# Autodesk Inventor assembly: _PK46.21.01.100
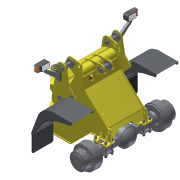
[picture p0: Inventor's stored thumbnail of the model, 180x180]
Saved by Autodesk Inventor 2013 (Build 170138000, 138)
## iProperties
Created: 2005-04
Part Number: _PK46.21.01.100
Document SubType Name: Assembly
Designer: salex
Manufacturer: Standard
Standards Organization: Custom
Author: salex
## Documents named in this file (46)
- C:\Product Design Suite 2013 Test Drive\Inventor to Showcase\Workspace\Assy, Chassis, Front\_PK46.21.01.100.iam
- C:\Product Design Suite 2013 Test Drive\Inventor to Showcase\Workspace\Assy, Chassis, Front\PK46.21.01.010.iam
- C:\Product Design Suite 2013 Test Drive\Inventor to Showcase\Workspace\Assy, Chassis, Front\PK46.21.01.020.iam
- C:\Product Design Suite 2013 Test Drive\Inventor to Showcase\Workspace\Assy, Chassis, Front\PK46.21.01.030.iam
- C:\Product Design Suite 2013 Test Drive\Inventor to Showcase\Workspace\Assy, Chassis, Front\PK46.21.01.040.iam
- C:\Product Design Suite 2013 Test Drive\Inventor to Showcase\Workspace\Assy, Chassis, Front\PK46.21.01.050.iam
- C:\Product Design Suite 2013 Test Drive\Inventor to Showcase\Workspace\Assy, Chassis, Front\PK46.21.01.060.iam
- C:\Product Design Suite 2013 Test Drive\Inventor to Showcase\Workspace\Assy, Chassis, Front\PK46.21.01.070.iam
- C:\Product Design Suite 2013 Test Drive\Inventor to Showcase\Workspace\Assy, Chassis, Front\PK46.21.01.025.ipt
- C:\Product Design Suite 2013 Test Drive\Inventor to Showcase\Workspace\Assy, Chassis, Front\PK46.21.01.026.ipt
- C:\Product Design Suite 2013 Test Drive\Inventor to Showcase\Workspace\Assy, Chassis, Front\PK46.21.01.027.ipt
- C:\Product Design Suite 2013 Test Drive\Inventor to Showcase\Workspace\Assy, Chassis, Front\PK46.21.01.028.ipt
- C:\Product Design Suite 2013 Test Drive\Inventor to Showcase\Workspace\Assy, Chassis, Front\PK46.21.01.029.ipt
- C:\Product Design Suite 2013 Test Drive\Inventor to Showcase\Workspace\Assy, Chassis, Front\PK46.21.01.031.ipt
- C:\Product Design Suite 2013 Test Drive\Inventor to Showcase\Workspace\Assy, Chassis, Front\027.32.02.621.ipt
- C:\Product Design Suite 2013 Test Drive\Inventor to Showcase\Workspace\Assy, Chassis, Front\Bar.ipt
- C:\Product Design Suite 2013 Test Drive\Inventor to Showcase\Workspace\Assy, Chassis, Front\PK46.21.01.035.ipt
- C:\Product Design Suite 2013 Test Drive\Inventor to Showcase\Workspace\Assy, Chassis, Front\PK46.21.01.036.ipt
- C:\Product Design Suite 2013 Test Drive\Inventor to Showcase\Workspace\Assy, Chassis, Front\PK46.21.01.032_1.ipt
- C:\Product Design Suite 2013 Test Drive\Inventor to Showcase\Workspace\Assy, Chassis, Front\_PK46.21.01.080.iam
- C:\Product Design Suite 2013 Test Drive\Inventor to Showcase\Workspace\Assy, Chassis, Front\ODM.73.001-6.iam
- C:\Product Design Suite 2013 Test Drive\Inventor to Showcase\Workspace\Assy, Chassis, Front\PK46.16.10.000.iam
- C:\Product Design Suite 2013 Test Drive\Inventor to Showcase\Workspace\Assy, Chassis, Front\PK46.04.00.002.ipt
- C:\Product Design Suite 2013 Test Drive\Inventor to Showcase\Workspace\Assy, Chassis, Front\PK46.04.00.030.iam
- C:\Product Design Suite 2013 Test Drive\Inventor to Showcase\Workspace\Assy, Chassis, Front\027.13.14.227.ipt
- C:\Product Design Suite 2013 Test Drive\Inventor to Showcase\Workspace\Assy, Chassis, Front\027.13.12.227.ipt
- C:\Product Design Suite 2013 Test Drive\Inventor to Showcase\Workspace\Assy, Chassis, Front\PK46.53.20.000.iam
- C:\Product Design Suite 2013 Test Drive\Inventor to Showcase\Workspace\Assy, Chassis, Front\Part 3.ipt
- C:\Product Design Suite 2013 Test Drive\Inventor to Showcase\Workspace\Assy, Chassis, Front\PK46.43.00.005.ipt
- C:\Product Design Suite 2013 Test Drive\Inventor to Showcase\Workspace\Assy, Chassis, Front\Flap.ipt
- C:\Product Design Suite 2013 Test Drive\Inventor to Showcase\Workspace\Assy, Chassis, Front\PK46.25.00.020.iam
- C:\Product Design Suite 2013 Test Drive\Inventor to Showcase\Workspace\Assy, Chassis, Front\PK46.25.00.006.ipt
- C:\Product Design Suite 2013 Test Drive\Inventor to Showcase\Workspace\Assy, Chassis, Front\PK46.25.00.008.ipt
- C:\Product Design Suite 2013 Test Drive\Inventor to Showcase\Workspace\Assy, Chassis, Front\PK46.25.00.007.ipt
- C:\Product Design Suite 2013 Test Drive\Inventor to Showcase\Workspace\Assy, Chassis, Front\PK46.25.00.010.iam
- C:\Product Design Suite 2013 Test Drive\Inventor to Showcase\Workspace\Assy, Chassis, Front\PK46.25.00.005.ipt
- C:\Product Design Suite 2013 Test Drive\Inventor to Showcase\Workspace\Assy, Chassis, Front\PK46.41.00.200-01.iam
- C:\Product Design Suite 2013 Test Drive\Inventor to Showcase\Workspace\Assy, Chassis, Front\PK46.20.10.000.iam
- C:\Product Design Suite 2013 Test Drive\Inventor to Showcase\Workspace\Assy, Chassis, Front\PK46.04.00.031.iam
- C:\Product Design Suite 2013 Test Drive\Inventor to Showcase\Workspace\Assy, Chassis, Front\027.13.15.227.ipt
- C:\Product Design Suite 2013 Test Drive\Inventor to Showcase\Workspace\Assy, Chassis, Front\027.13.16.227.ipt
- C:\Product Design Suite 2013 Test Drive\Inventor to Showcase\Workspace\Assy, Chassis, Front\PK46.41.00.200-02.iam
- C:\Product Design Suite 2013 Test Drive\Inventor to Showcase\Workspace\Assy, Chassis, Front\PK46.53.20.001.iam
- Bar.ipt
- Part 3.ipt
- Flap.ipt
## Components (106 placed, 42 different names)
1. PK46.21.01.010:1 [sub-assembly] — Mate:1, Mate:3, Mate:6, Mate:9, Angle:1, Mate:10, Flush:3, Angle:4, Mate:17, Mate:18, Mate:19, Mate:33, Mate:34, Mate:45, Mate:54, Mate:61, Mate:67, Mate:68, Mate:73, Angle:8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
2. PK46.21.01.020:1 [sub-assembly] — Mate:2, Mate:4, Mate:6, Mate:8, Mate:39, Mate:40, Mate:59, Mate:66, Mate:69, Mate:72, Angle:7, Flush:16, Mate:100
3. PK46.21.01.030:1 [sub-assembly] — Mate:17, Mate:23, Mate:24, Mate:25, Tangent:1, Tangent:2, Tangent:3, Mate:79, Mate:80
4. PK46.21.01.040:1 [sub-assembly] — Mate:3, Mate:4, Mate:7, Flush:2, Mate:13, Angle:2, Angle:5
5. PK46.21.01.050:1 [sub-assembly] — Mate:1, Mate:2, Mate:7, Flush:2, Angle:4, Angle:6, Mate:55, Mate:64, Mate:65, Mate:70, Mate:71
6. PK46.21.01.060:1 [sub-assembly] — Mate:9, Flush:1, Angle:1, Mate:10, Mate:11, Flush:3, Mate:16, Mate:35, Mate:36, Mate:37, Mate:38, Mate:46, Mate:50, Mate:56, Flush:5, Mate:47, Mate:75
7. PK46.21.01.070:1 [sub-assembly] — Mate:8, Flush:1, Mate:11, Mate:41, Mate:42, Mate:43, Mate:44, Mate:49, Mate:53, Mate:57, Flush:6
8. _PK46.21.01.080:1 [sub-assembly] — Mate:32, Mate:54, Mate:55, Angle:9
9. ODM.73.001-6:1 [sub-assembly]
10. Flap:1
11. PK46.53.20.000:1 [sub-assembly]
12. PK46.25.00.020:4 [sub-assembly]
13. PK46.25.00.006:5
14. PK46.41.00.200-01:1 [sub-assembly]
15. PK46.43.00.005:1
16. PK46.43.00.005:2
17. PK46.25.00.006:8
18. PK46.25.00.008:4
19. PK46.25.00.007:4
20. PK46.25.00.010:1 [sub-assembly]
21. PK46.25.00.005:1
22. PK46.25.00.007:2
23. PK46.25.00.008:2
24. PK46.25.00.006:4
25. PK46.25.00.006:3
26. PK46.25.00.020:1 [sub-assembly]
27. PK46.04.00.002:1
28. PK46.04.00.030:1 [sub-assembly]
29. PK46.04.00.030:2 [sub-assembly]
30. PK46.04.00.030:3 [sub-assembly]
31. PK46.04.00.030:4 [sub-assembly]
32. 027.13.14.227:1
33. 027.13.14.227:2
34. 027.13.14.227:3
35. 027.13.14.227:4
36. 027.13.12.227:1
37. 027.13.12.227:2
38. 027.13.12.227:3
39. 027.13.12.227:4
40. PK46.16.10.000:1 [sub-assembly]
41. Part 3:1
42. Part 3:2
43. PK46.20.10.000:3 [sub-assembly]
44. PK46.20.10.000:4 [sub-assembly]
45. PK46.04.00.031:3 [sub-assembly]
46. PK46.04.00.031:4 [sub-assembly]
47. 027.13.15.227:3
48. 027.13.15.227:4
49. 027.13.16.227:3
50. 027.13.16.227:4
51. PK46.53.20.001:1 [sub-assembly]
52. PK46.25.00.020:3 [sub-assembly]
53. PK46.25.00.020:2 [sub-assembly]
54. PK46.25.00.006:2
55. PK46.25.00.008:1
56. PK46.25.00.007:1
57. PK46.25.00.008:3
58. PK46.25.00.007:3
59. PK46.25.00.006:7
60. PK46.25.00.005:2
61. PK46.25.00.008:5
62. PK46.25.00.007:5
63. PK46.43.00.005:3
64. PK46.43.00.005:4
65. PK46.25.00.006:1
66. PK46.25.00.006:6
67. PK46.41.00.200-02:1 [sub-assembly]
68. PK46.04.00.030:5 [sub-assembly]
69. PK46.04.00.030:7 [sub-assembly]
70. 027.13.14.227:5
71. 027.13.14.227:8
72. 027.13.12.227:5
73. 027.13.12.227:8
74. PK46.04.00.030:6 [sub-assembly]
75. PK46.04.00.030:8 [sub-assembly]
76. 027.13.14.227:6
77. 027.13.14.227:7
78. 027.13.12.227:6
79. 027.13.12.227:7
80. 027.13.16.227:1
81. 027.13.15.227:1
82. PK46.04.00.031:1 [sub-assembly]
83. PK46.20.10.000:1 [sub-assembly]
84. 027.13.16.227:2
85. 027.13.15.227:2
86. PK46.04.00.031:2 [sub-assembly]
87. PK46.20.10.000:2 [sub-assembly]
88. PK46.21.01.032_1:1
89. PK46.21.01.032_1:2
90. PK46.21.01.025:1 — Mate:45, Mate:46, Flush:4, Mate:47, Mate:48, Mate:74
91. PK46.21.01.026:1 — Mate:52, Mate:53, Mate:58, Mate:60, Flush:4
92. PK46.21.01.027:1 — Mate:49, Mate:50, Mate:51, Mate:52, Mate:48
93. PK46.21.01.028:1 — Mate:56, Mate:58, Mate:61
94. PK46.21.01.028:2 — Mate:57, Mate:59, Mate:60
95. PK46.21.01.029:1 — Mate:64, Mate:67
96. PK46.21.01.029:2 — Mate:65, Mate:66
97. PK46.21.01.031:1 — Mate:68, Flush:5, Mate:70
98. PK46.21.01.031:2 — Mate:69, Flush:6, Mate:71
99. 027.32.02.621:1 — Mate:33, Mate:36, Mate:37
100. 027.32.02.621:2 — Mate:34, Mate:35, Mate:38
101. 027.32.02.621:3 — Mate:40, Mate:41, Mate:44
102. 027.32.02.621:4 — Mate:39, Mate:42, Mate:43
103. PK46.21.01.036:1 — Mate:72, Tangent:1, Tangent:2, Angle:7
104. PK46.21.01.035:1 — Mate:73, Mate:74, Angle:8, Tangent:3, Mate:76
105. Bar:1 — Mate:78, Angle:9, Mate:79, Mate:80, Flush:7, Flush:8
106. Bar:2 — Flush:7, Flush:8
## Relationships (85: Mate 65, Flush 9, Angle 8, Tangent 3)
- Mate:1: PK46.21.01.010:1 ↔ PK46.21.01.050:1
- Mate:2: PK46.21.01.020:1 ↔ PK46.21.01.050:1
- Mate:3: PK46.21.01.010:1 ↔ PK46.21.01.040:1
- Mate:4: PK46.21.01.020:1 ↔ PK46.21.01.040:1
- Mate:6: PK46.21.01.010:1 ↔ PK46.21.01.020:1
- Mate:7: PK46.21.01.040:1 ↔ PK46.21.01.050:1
- Mate:8: PK46.21.01.020:1 ↔ PK46.21.01.070:1
- Mate:9: PK46.21.01.010:1 ↔ PK46.21.01.060:1
- Flush:1: PK46.21.01.060:1 ↔ PK46.21.01.070:1
- Angle:1: PK46.21.01.010:1 ↔ PK46.21.01.060:1
- Mate:10: PK46.21.01.010:1 ↔ PK46.21.01.060:1
- Mate:11: PK46.21.01.060:1 ↔ PK46.21.01.070:1
- Flush:2: PK46.21.01.040:1 ↔ PK46.21.01.050:1
- Flush:3: PK46.21.01.010:1 ↔ PK46.21.01.060:1
- Mate:13: PK46.21.01.040:1
- Angle:2: PK46.21.01.040:1
- Angle:4: PK46.21.01.010:1 ↔ PK46.21.01.050:1
- Angle:5: PK46.21.01.040:1
- Mate:16: PK46.21.01.060:1
- Mate:17: PK46.21.01.010:1 ↔ PK46.21.01.030:1
- Mate:18: PK46.21.01.010:1
- Mate:19: PK46.21.01.010:1
- Angle:6: PK46.21.01.050:1
- Mate:23: PK46.21.01.030:1
- Mate:24: PK46.21.01.030:1
- Mate:25: PK46.21.01.030:1
- Mate:32: _PK46.21.01.080:1
- Mate:33: PK46.21.01.010:1 ↔ 027.32.02.621:1
- Mate:34: PK46.21.01.010:1 ↔ 027.32.02.621:2
- Mate:35: PK46.21.01.060:1 ↔ 027.32.02.621:2
- Mate:36: PK46.21.01.060:1 ↔ 027.32.02.621:1
- Mate:37: PK46.21.01.060:1 ↔ 027.32.02.621:1
- Mate:38: PK46.21.01.060:1 ↔ 027.32.02.621:2
- Mate:39: PK46.21.01.020:1 ↔ 027.32.02.621:4
- Mate:40: PK46.21.01.020:1 ↔ 027.32.02.621:3
- Mate:41: PK46.21.01.070:1 ↔ 027.32.02.621:3
- Mate:42: PK46.21.01.070:1 ↔ 027.32.02.621:4
- Mate:43: PK46.21.01.070:1 ↔ 027.32.02.621:4
- Mate:44: PK46.21.01.070:1 ↔ 027.32.02.621:3
- Mate:45: PK46.21.01.010:1 ↔ PK46.21.01.025:1
- Mate:46: PK46.21.01.060:1 ↔ PK46.21.01.025:1
- Mate:49: PK46.21.01.070:1 ↔ PK46.21.01.027:1
- Mate:50: PK46.21.01.060:1 ↔ PK46.21.01.027:1
- Mate:51: PK46.21.01.027:1
- Mate:52: PK46.21.01.026:1 ↔ PK46.21.01.027:1
- Mate:53: PK46.21.01.070:1 ↔ PK46.21.01.026:1
- Mate:54: PK46.21.01.010:1 ↔ _PK46.21.01.080:1
- Mate:55: PK46.21.01.050:1 ↔ _PK46.21.01.080:1
- Mate:56: PK46.21.01.060:1 ↔ PK46.21.01.028:1
- Mate:57: PK46.21.01.070:1 ↔ PK46.21.01.028:2
- Mate:58: PK46.21.01.026:1 ↔ PK46.21.01.028:1
- Mate:59: PK46.21.01.020:1 ↔ PK46.21.01.028:2
- Mate:60: PK46.21.01.026:1 ↔ PK46.21.01.028:2
- Mate:61: PK46.21.01.010:1 ↔ PK46.21.01.028:1
- Mate:64: PK46.21.01.050:1 ↔ PK46.21.01.029:1
- Mate:65: PK46.21.01.050:1 ↔ PK46.21.01.029:2
- Mate:66: PK46.21.01.020:1 ↔ PK46.21.01.029:2
- Mate:67: PK46.21.01.010:1 ↔ PK46.21.01.029:1
- Mate:68: PK46.21.01.010:1 ↔ PK46.21.01.031:1
- Mate:69: PK46.21.01.020:1 ↔ PK46.21.01.031:2
- Flush:5: PK46.21.01.060:1 ↔ PK46.21.01.031:1
- Flush:6: PK46.21.01.070:1 ↔ PK46.21.01.031:2
- Mate:70: PK46.21.01.050:1 ↔ PK46.21.01.031:1
- Mate:71: PK46.21.01.050:1 ↔ PK46.21.01.031:2
- Flush:4: PK46.21.01.025:1 ↔ PK46.21.01.026:1
- Mate:47: PK46.21.01.060:1 ↔ PK46.21.01.025:1
- Mate:48: PK46.21.01.025:1 ↔ PK46.21.01.027:1
- Mate:72: PK46.21.01.020:1 ↔ PK46.21.01.036:1
- Tangent:1: PK46.21.01.030:1 ↔ PK46.21.01.036:1
- Tangent:2: PK46.21.01.030:1 ↔ PK46.21.01.036:1
- Angle:7: PK46.21.01.020:1 ↔ PK46.21.01.036:1
- Mate:73: PK46.21.01.010:1 ↔ PK46.21.01.035:1
- Mate:74: PK46.21.01.025:1 ↔ PK46.21.01.035:1
- Angle:8: PK46.21.01.010:1 ↔ PK46.21.01.035:1
- Tangent:3: PK46.21.01.030:1 ↔ PK46.21.01.035:1
- Mate:75: PK46.21.01.060:1
- Mate:76: PK46.21.01.035:1
- Mate:78: PK46.21.01.010:1 ↔ Bar:1
- Angle:9: _PK46.21.01.080:1 ↔ Bar:1
- Mate:79: PK46.21.01.030:1 ↔ Bar:1
- Mate:80: PK46.21.01.030:1 ↔ Bar:1
- Flush:7: Bar:1 ↔ Bar:2
- Flush:8: Bar:1 ↔ Bar:2
- Flush:16: PK46.21.01.020:1
- Mate:100: PK46.21.01.020:1
## Named parameters: d389_d402 = 0, d390_d403 = 0, d391_d404 = 0, d392_d405 = 0, d393_d406 = 0, d394_d407 = 0, d395_d408 = 0, d396_d409 = 0, d397_d410 = 0, d398_d411 = 0, d399_d412 = 0, d400_d413 = 0, d401_d415 = 0, d402_d416 = 0, d403_d417 = 0, d404_d418 = 0, d405_d419 = 0, d406_d420 = 0, d407_d421 = 0, d408_d422 = 0, d409_d423 = 0, d410_d424 = 0, d411_d425 = 0, d431_d156 = 0, d432_d159 = 0, d433_d161 = 0, d435_d165 = 0, d443_d127 = 0, d456_d88 = 0, d457_d90 = 0
